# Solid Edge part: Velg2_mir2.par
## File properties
Author: KULL
Template: Iso Metric Part.par
Last saved by: KULL
Revision: 2
Application: Solid Edge
Accuracy: 0,990
Username: KULL
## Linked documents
Velg2.par
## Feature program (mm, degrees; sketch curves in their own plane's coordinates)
part copy "CopiedPart_1"
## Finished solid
Body 1: solid body, 389 faces, 931 edges, 512 vertices.
  Faces by surface: blend 256, torus 63, swept 32, cylinder 24, cone 10, plane 2, spun 2
  Edges by curve: intersection 512, circle 403, line 16
Bounding box of the edges (mm; curved faces can reach further): 43.118 x 87.299 x 87.299, from (-41.1766, -43.6493, -43.6493) to (1.9413, 43.6493, 43.6493).
Cylindrical faces by radius (mm): R4 x1, R8 x1, R10 x1, R36.3826 x1, R38.3116 x17, R38.3826 x1, R40.3116 x2
Conical faces (half-angle, radius in mm at the cone's reference point): 14.1898 deg R43.1591 x1, 14.1898 deg R43.6493 x1, 17.3646 deg R36.5649 x1, 17.3646 deg R38.1293 x1, 17.3646 deg R38.5649 x1, 17.3646 deg R40.1293 x1, 75.8102 deg R41.0291 x1, 75.8102 deg R41.5194 x1, 75.8102 deg R43.1591 x1, 75.8102 deg R43.6493 x1
Toroidal faces (ring radius, tube radius in mm): R8.1 r0.1 x1, R13 r3 x1, R34.3116 r4 x17, R36.3116 r4 x2, R36.7771 r0.6 x16, R38.0022 r0.6 x16, R40.3826 r4 x2, R41.9116 r1.6 x2, R41.9116 r3.6 x2, R42.3826 r4 x2, R43.0142 r0.2 x2
Planar faces by outward normal: +x 1, -x 1
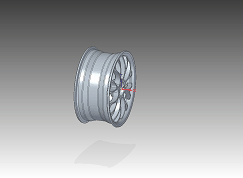
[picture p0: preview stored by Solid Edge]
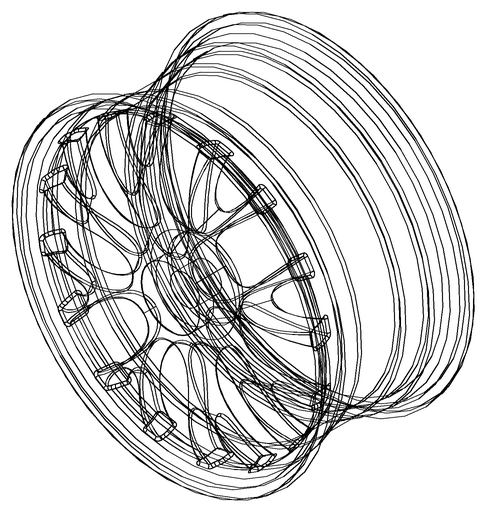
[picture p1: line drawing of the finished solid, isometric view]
